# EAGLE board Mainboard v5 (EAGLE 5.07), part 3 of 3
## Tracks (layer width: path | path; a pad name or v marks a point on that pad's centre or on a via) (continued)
N$145 (continued)
  Top 0.406: IC7.10 R83.2 33.5,109.53 34.45,108.58 35.4,107.64 R77.2
N$146  (via drill 0.3)
  Top 0.254: R11.2 v86.84,75.56
  Top 0.305: R11.2
  Top 0.406: R11.2 IC1.10
  Bottom 0.254: v86.84,75.56 v86.83,75.56 R5.1
N$147  (via drill 0.3)
  Top 0.61: IC7.16 25.88,113.67 25.88,110.49 v25.88,103.19
  Bottom 0.61: v25.88,103.19 23.65,103.19 R75.1
N$148  (via drill 0.3)
  Top 0.254: v5.24,81.92 5.56,81.92 R30.2
  Bottom 0.254: M2.3 6.02,83.01 5.24,82.23 v5.24,81.92
N$149
  Top 0.254: IC37.31 94.23,14.51 94.78,13.97 96.36,13.97 97,14.61 99.22,14.61 LED11.C
N$150
  Top 0.254: C113.1 52.87,26.67 R153.1 50.33,26.35 50.01,26.35 48.78,25.13 IC31.5
N$151
  Top 0.254: R157.2 46.83,29.84 47.28,29.39 IC31.9
N$152
  Top 0.254: IC37.32 97.47,15.39 98.27,16.19 100.39,16.19 LED12.C
N$153
  Top 0.254: IC37.1 99.91,16.89 100.49,17.46 101.81,17.46 LED13.C
N$154
  Top 0.406: 35.4,111.12 R83.1 | 35.4,111.12 R87.2 | IC7.11 35.4,111.12
N$156
  Top 0.254: IC37.2 99.76,17.68 100.81,18.73 103.24,18.73 LED14.C
N$157  (via drill 0.3)
  Top 0.254: 77.31,120.97 R137.2 R136.2 | 77.31,120.97 R138.2 R134.2 R135.2 69.06,120.97 Q34.3 | 77.31,120.97 77.31,123.83 77,124.14 77,125.09 | 77,125.09 SDCARD.4 | 77,125.09 77,126.05 v77.63,126.68
  Bottom 0.254: v77.63,126.68 79.85,126.68 R133.2
N$158
  Top 0.406: FLT5.C 29.05,93.67 R73.1
N$159
  Top 0.254: IC37.9 100.69,23.98 LED15.C
N$160
  Top 0.254: IC37.10 94.23,24.86 94.46,25.08 102.28,25.08 LED16.C
N$161
  Top 0.254: IC37.11 93.44,24.7 94.46,25.72 104.33,25.72 LED17.C
N$162  (via drill 0.3)
  Top 0.61: IC7.27 23.97,99.69 v23.97,99.38
  Bottom 0.61: v23.97,99.38 23.97,98.42 R74.1
N$163
  Top 0.406: IC7.9 32.23,108.58 R77.1
N$164
  Top 0.254: IC37.12 92.64,24.85 94.14,26.35 106.39,26.35 LED18.C
N$165
  Top 0.254: IC29.24 59,105.2 59.53,105.73 59.53,107 59.53,109.22 58.26,110.49 R148.2
N$166
  Top 0.254: IC37.13 91.83,25 93.82,26.99 108.45,26.99 LED19.C
N$167
  Bottom 0.254: C141.1 R207.1
N$168
  Top 0.254: IC29.23 59.5,105.06 60.17,105.73 60.17,106.68 60.17,107.31 60.17,109.54 59.53,110.17 59.53,112.08 60.48,113.03 62.07,113.03 63.34,114.3 63.34,115.57 | 63.34,115.57 63.34,116.14 Q35.1 | C93.1 67.47,115.57 63.34,115.57
N$169
  Top 0.254: R148.1 53.75,114.68 53.75,115.57 | 53.75,115.57 Q35.2 | C94.1 49.69,115.57 53.75,115.57
N$170
  Bottom 0.254: C142.1 R208.1
N$171
  Top 0.254: R149.1 65.25,110.17 Q36.2 C96.1
N$172
  Bottom 0.254: C143.1 R209.1
N$173
  Bottom 0.406: R145.2 JTAG.11
N$174
  Top 0.254: R158.2 43.02,30.48 44.61,28.89 46.76,28.89 IC31.10
N$175  (via drill 0.3)
  Top 0.254: v44.93,29.53 C115.1
  Bottom 0.254: C115.1 44.93,30.16 v44.93,29.53
N$176
  Bottom 0.254: IC28.5 75.72,128.27 73.82,128.27 C88.1 71.92,128.91 71.92,130.18 72.87,131.13 72.87,132.4 USB.1 74.14,132.4
N$177
  Bottom 0.254: USB.2 74.77,130.18 IC28.1
N$178
  Bottom 0.254: USB.3 75.72,130.81 76.68,130.81 76.68,130.49 IC28.3
N$179
  Bottom 0.254: IC27.6 90.65,128.59 92.23,130.18 92.23,131.76 C86.1
N$180
  Bottom 0.254: IC27.2 90.65,126.05 90.97,125.73 90.97,123.51 C87.1
N$181
  Bottom 0.254: 96.05,126.68 96.02,126.66 IC27.14 97.31,126.68 98.58,127.95 98.58,129.86 94.46,133.99 93.19,133.99 92.87,134.3 92.87,138.43 92.23,139.06 88.42,139.06 PC.1
N$182
  Bottom 0.254: IC27.3 88.42,126.68 C85.2
N$183
  Bottom 0.254: IC27.1 89.38,125.41 88.42,124.46 88.11,124.46 C85.1
N$184
  Bottom 0.254: IC27.4 88.74,127.32 C89.1
N$185
  Bottom 0.254: IC27.5 89.38,127.95 89.06,128.27 89.06,128.91 C89.2
N$186
  Bottom 0.254: IC27.13 97,127.32 97.95,128.27 97.95,129.54 94.14,133.35 92.87,133.35 PC.2
N$187
  Top 0.254: R161.1 45.88,27.94 48.28,27.94 IC31.7
N$188
  Bottom 0.61: Q9.4 R28.2
N$189  (via drill 0.3)
  Top 0.61: Q10.4 v19.53,79.38
  Bottom 0.61: v19.53,79.38 R32.2
N$190
  Bottom 0.61: R34.2 19.53,81.92 Q11.4
N$191  (via drill 0.3)
  Top 0.61: Q12.4 v19.53,85.72
  Bottom 0.61: v19.53,85.72 R35.2
N$193
  Top 0.254: R125.2 53.5,37.47 Q32.B
N$194
  Top 0.254: R126.2 53.5,33.8 Q33.B
N$195
  Top 0.254: IC26.13 63.66,37.47 R125.1
N$196
  Top 0.254: IC26.14 63.66,29.21 54.77,29.21 R126.1
N$197
  Top 0.254: C111.1 46.52,22.86 47.28,23.63 IC31.2
N$198
  Top 0.254: 47.78,19.05 IC31.3 | 47.78,19.05 46.83,19.05 C111.2 44.93,19.37 43.02,17.46 42.07,17.46 L2.P$2 | D23.C 49.05,18.41 48.42,19.05 47.78,19.05
  pour Top (no thermals): 40.16,18.1 43.02,18.1 44.93,20 50.64,20 50.64,17.14 45.24,17.14 44.61,16.51 40.16,16.51
N$200  (via drill 0.3)
  Top 0.254: R159.2 v48.42,30.8 47.78,30.16 IC31.8
  Bottom 0.254: v48.42,30.8 R159.2
N$201
  Top 0.254: R167.2 arc-90 47.15,14.61 47.28,14.47 IC34.9
N$202
  Top 0.254: R168.2 43.02,14.61 44.61,13.02 46.76,13.02 IC34.10
N$203  (via drill 0.3)
  Top 0.254: v44.93,13.65 C120.1
  Bottom 0.254: C120.1 44.93,14.29 v44.93,13.65
N$204
  Top 0.254: R175.1 45.88,12.06 48.28,12.06 IC34.7
N$205
  Top 0.254: C116.1 46.52,6.99 47.28,7.75 IC34.2
N$206
  Top 0.254: 47.78,3.17 IC34.3 | 47.78,3.17 46.83,3.17 C116.2 44.93,3.49 43.34,1.91 42.39,1.91 L3.P$2 | D25.C 49.37,2.86 49.05,3.17 47.78,3.17
  pour Top (no thermals): 40.16,2.22 43.02,2.22 44.93,4.13 50.64,4.13 50.64,1.27 45.24,1.27 44.61,0.64 40.16,0.64
N$207  (via drill 0.3)
  Top 0.254: IC34.8 47.78,14.29 v48.42,14.92 R173.2
  Bottom 0.254: v48.42,14.92 R173.2
N$213
  Bottom 0.61: Q13.4 R38.2
N$215  (via drill 0.3)
  Top 0.61: Q14.4 v19.53,41.91
  Bottom 0.61: v19.53,41.91 R39.2
N$216  (via drill 0.3)
  Top 0.254: v3.97,31.43 R45.2
  Bottom 0.254: M3.2 6.32,31.88 5.88,31.43 v3.97,31.43
N$217  (via drill 0.3)
  Top 0.254: v12.86,31.43 R49.2
  Bottom 0.254: M3.4 8.32,32.48 8.73,32.07 12.23,32.07 v12.86,31.43
N$222  (via drill 0.3)
  Top 0.254: v8.41,31.43 R48.2
  Bottom 0.254: M3.3 7.32,31.89 7.78,31.43 v8.41,31.43
N$223
  Bottom 0.61: Q15.4 R46.2
N$224  (via drill 0.3)
  Top 0.61: Q16.4 v19.53,48.26
  Bottom 0.61: v19.53,48.26 R50.2
N$225
  Bottom 0.61: Q17.4 R52.2
N$226  (via drill 0.3)
  Top 0.61: Q18.4 v19.53,54.61
  Bottom 0.61: v19.53,54.61 R53.2
N$234
  Bottom 0.61: Q19.4 100.49,55.88 R56.2
N$236  (via drill 0.3)
  Top 0.61: v100.49,52.07 Q20.4
  Bottom 0.61: R57.2 v100.49,52.07
N$237  (via drill 0.3)
  Top 0.254: v103.03,33.34 R63.2
  Bottom 0.254: M4.2 105.38,32.51 104.94,32.07 103.67,32.07 103.03,32.7 v103.03,33.34
N$238  (via drill 0.3)
  Top 0.254: v111.92,31.75 111.92,33.02 112.24,33.34 R67.2
  Bottom 0.254: M4.4 107.38,32.8 108.43,31.75 v111.92,31.75
N$243  (via drill 0.3)
  Top 0.254: v107.47,31.75 107.47,33.02 107.79,33.34 R66.2
  Bottom 0.254: M4.3 106.38,32.53 107.16,31.75 v107.47,31.75
N$244
  Bottom 0.61: R64.2 Q21.4
N$245  (via drill 0.3)
  Top 0.61: v100.49,45.72 Q22.4
  Bottom 0.61: R68.2 v100.49,45.72
N$246
  Bottom 0.61: R70.2 Q23.4
N$247  (via drill 0.3)
  Top 0.61: v100.49,39.37 Q24.4
  Bottom 0.61: R71.2 v100.49,39.37
N$255
  Bottom 0.61: Q25.4 R74.2
N$257  (via drill 0.3)
  Top 0.61: Q26.4 v19.53,102.23
  Bottom 0.61: v19.53,102.23 R75.2
N$258
  Top 0.254: R81.2 10.95,117.16 8.1,117.16 M5.2
N$259
  Top 0.254: R85.2 17.3,115.89 9.05,115.89 5.88,112.71 5.88,109.86 M5.4
N$264
  Top 0.254: R84.2 14.13,116.52 8.73,116.52 5.24,113.03 5.24,111.76 M5.3
N$265
  Bottom 0.61: Q27.4 R82.2
N$266  (via drill 0.3)
  Top 0.61: Q28.4 v19.53,108.58
  Bottom 0.61: v19.53,108.58 R86.2
N$267
  Bottom 0.61: Q29.4 R88.2
N$268  (via drill 0.3)
  Top 0.61: Q30.4 v19.53,114.94
  Bottom 0.61: v19.53,114.94 R89.2
OSC32-IN
  Top 0.254: IC29.8 67,105.88 66.52,106.36 66.52,110.81 Q36.1 68.42,111.12 C95.1
OSC32-OUT
  Top 0.254: IC29.9 66.5,105.42 R149.2
PADC-VOP
  Top 0.254: 80.17,14.61 C133.1 78.58,14.61 | 75.09,14.61 78.58,14.61 | 78.58,14.61 80.17,14.61 | IC35.4 69.06,14.61 75.09,14.61 | 75.09,14.61 IC36.4 | 80.17,14.61 80.49,14.61 R192.2
PC-RXD  (via drill 0.3)
  Top 0.254: IC29.102 67.5,84.17 67.79,84.45 v67.79,88.9 | v90.97,113.67 90.97,124.46 94.78,128.27 v97,128.27
  Bottom 0.254: IC27.12 96.68,127.95 v97,128.27 | v67.79,88.9 73.5,94.61 73.5,102.23 80.49,109.22 87.79,109.22 90.97,112.39 v90.97,113.67
PC-TXD  (via drill 0.3)
  Top 0.254: IC29.101 67,84.31 67.15,84.45 v67.15,89.53 | v97,129.22 94.46,129.22 89.69,124.46 v89.69,113.67
  Bottom 0.254: IC27.11 96.05,128.59 96.36,128.59 v97,129.22 | v67.15,89.53 72.87,95.25 72.87,102.55 80.17,109.86 85.89,109.86 v89.69,113.67
PWR+
  Bottom 0.406: 42.7,3.17 38.26,7.62 F1.P$1 | BAT1+.P$1 61.75,5.71 R169.2
  pour Bottom (no thermals): 31.27,8.26 31.91,8.89 38.9,8.89 43.98,3.81 57.94,3.81 59.22,2.54 59.22,1.27 58.58,0.64 42.07,0.64 36.35,6.35 31.91,6.35 31.27,6.99
PWR-AREF
  Top 0.254: R206.1 83.03,25.72 81.12,25.72 80.57,25.17 C139.+ 80.17,24.68 80.17,22.07 D26.1 C140.1 85.57,21.91 87.39,20.09 IC37.20
PWR-AVCC
  Top 0.254: IC37.18 87.06,21.68 86.84,21.91 86.84,23.66 L4.2 87,24.13 C138.1 R206.2
PWR-CS  (via drill 0.3)
  Top 0.254: IC29.73 53.01,83.64 53.82,84.45 v56.36,84.45 | v75.09,48.26 73.19,48.26 v70.01,51.44 | v90.65,26.67 90.65,25.72 91.03,25.33 IC37.14
  Bottom 0.254: v56.36,84.45 56.99,84.45 61.12,80.33 61.12,77.47 70.01,68.26 v70.01,51.44 | v75.09,48.26 90.65,32.7 v90.65,26.67
PWR-RST  (via drill 0.3)
  Top 0.254: IC29.65 52.4,88.09 52.87,87.63 v54.77,87.63 | v75.09,49.21 73.5,49.21 v70.64,52.07 | IC37.29 92.64,14.05 v92.55,13.97 R195.1 C136.1
  Bottom 0.254: v54.77,87.63 61.75,80.64 61.75,77.47 70.64,68.58 v70.64,52.07 | v75.09,49.21 91.28,33.02 91.28,15.24 v92.55,13.97
PWR-XTAL  (via drill 0.3)
  Top 0.254: v97.95,21.91 97.73,21.68 IC37.7
  Bottom 0.254: QG2.3 98.28,22.23 v97.95,21.91
SD-CD  (via drill 0.3)
  Top 0.152: IC29.114 74.04,87.09 76.68,84.45 v77,84.45
  Top 0.254: SDCARD.CD 83.34,133.03 v84.61,133.03 84.61,128.91 88.42,125.09 v88.42,106.05
  Bottom 0.254: R133.1 84.3,133.03 v84.61,133.03 | v77,84.45 77.95,84.45 81.76,88.27 81.76,97.79 88.42,104.46 v88.42,106.05
SD-CLK  (via drill 0.3)
  Top 0.152: IC29.113 73.9,86.59 76.36,84.14 v76.36,83.82
  Top 0.254: SDCARD.5 77.95,125.73 79.22,127 82.71,127 85.89,123.83 v85.89,104.14
  Bottom 0.254: v76.36,83.82 76.36,87 77.63,87 79.85,89.22 79.85,98.74 85.25,104.14 v85.89,104.14
SD-CMD  (via drill 0.3)
  Top 0.152: IC29.116 74.94,88.09 75.09,87.95 75.09,87.31 76.04,86.36 v77,86.36
  Top 0.254: 76.04,124.97 SDCARD.3 | 76.04,124.97 R138.1 | 76.04,124.97 76.04,126.48 77.31,127.64 83.03,127.64 86.52,124.14 v86.52,103.5
  Bottom 0.254: v77,86.36 77.95,86.36 80.49,88.9 80.49,98.42 85.57,103.5 v86.52,103.5
SD-D0  (via drill 0.3)
  Top 0.254: R137.1 | R137.1 80.17,123.19 80.17,125.09 SDCARD.7 | R137.1 80.17,122.56 80.17,121.92 83.34,121.92 84.61,120.65 v84.61,111.12 | IC29.98 65.5,89.79 65.25,90.05 v65.25,91.12
  Bottom 0.254: v65.25,91.12 71.6,97.16 71.6,103.19 79.53,111.12 v84.61,111.12
SD-D1  (via drill 0.3)
  Top 0.254: SDCARD.8 81.44,125.09 81.44,123.19 81.76,122.87 R136.1 83.34,122.87 85.25,120.97 v85.25,110.49 | IC29.99 66,90.29 65.88,90.42 v65.88,90.49
  Bottom 0.254: v65.88,90.49 72.23,96.52 72.23,102.87 79.85,110.49 v85.25,110.49
SD-D2  (via drill 0.3)
  Top 0.152: IC29.111 73.63,85.59 74.45,84.77 v74.45,83.82
  Top 0.254: R135.1 73.5,124.78 SDCARD.1 73.5,125.73 76.68,128.91 83.66,128.91 87.79,124.78 v87.79,105.41
  Bottom 0.254: v74.45,83.82 74.45,87.63 77.31,90.49 77.31,92.08 78.58,93.34 78.58,99.38 84.61,105.41 v87.79,105.41
SD-D3  (via drill 0.3)
  Top 0.152: IC29.112 73.77,86.09 75.41,84.45 v75.41,83.82
  Top 0.254: R134.1 74.77,123.83 74.77,125.09 | 74.77,125.09 SDCARD.2 | 74.77,125.09 74.77,126.05 77,128.27 83.34,128.27 87.16,124.46 v87.16,104.78
  Bottom 0.254: v75.41,83.82 75.41,87.31 77.95,89.85 77.95,91.76 79.22,93.03 79.22,99.06 84.93,104.78 v87.16,104.78
SD-PWR  (via drill 0.3)
  Top 0.152: v77,85.41 76.36,85.41 74.17,87.59 IC29.115
  Top 0.254: R127.1 67.79,126.68 | 69.38,125.09 69.38,122.87 Q34.1 69.38,125.09 | 67.79,126.68 69.38,125.09 | 67.79,126.68 66.83,126.68 66.2,126.05 66.2,120.97 67.47,119.7 73.19,119.7 74.14,118.75 76.36,118.75 82.71,112.39 82.71,104.78 v85.25,102.23
  Bottom 0.254: v77,85.41 77.95,85.41 81.12,88.58 81.12,98.11 v85.25,102.23
SPI1-MISO  (via drill 0.3)
  Top 0.254: v83.66,94.61 84.93,95.89 v102.39,95.89 | v56.04,90.81 56.04,96.2 52.65,99.59 IC29.42 49.59,99.59 49.37,99.38 45.24,99.38 45.24,118.11 v46.2,119.06 | IC25.9 58.4,130.31 v58.26,130.18
  Bottom 0.254: v56.04,90.81 62.71,90.81 71.92,81.6 77.95,81.6 83.66,87.63 v83.66,94.61 | v46.2,119.06 46.2,120.02 R120.2 46.2,120.02 v46.2,119.06 | v46.2,119.06 46.83,118.43 49.69,118.43 50.33,119.06 54.45,119.06 58.58,123.19 58.58,129.22 58.26,129.54 v58.26,130.18 | v102.39,95.89 103.03,95.89 108.11,100.97 108.11,105.72 R116.1
SPI1-MOSI  (via drill 0.3)
  Top 0.254: v84.3,93.98 85.57,95.25 v103.03,95.25 | v56.67,90.17 55.41,90.17 55.41,95.89 52.2,99.09 IC29.43 49.73,99.09 49.37,98.74 44.61,98.74 44.61,118.43 v43.98,119.06 | IC25.10 59.2,130.19 v59.22,130.18
  Bottom 0.254: v56.67,90.17 62.39,90.17 71.6,80.96 78.27,80.96 84.3,87.31 v84.3,93.98 | v43.98,119.06 R121.2 v43.98,119.06 | v43.98,119.06 45.24,117.79 50.01,117.79 50.64,118.43 54.77,118.43 59.22,122.87 v59.22,130.18 | v103.03,95.25 103.35,95.25 108.75,100.65 108.75,103.82 R117.2
SPI1-SCK  (via drill 0.3)
  Top 0.254: v83.03,93.98 83.03,94.93 84.61,96.52 v101.76,96.52 | v56.67,91.44 56.67,96.52 53.1,100.09 IC29.41 49.45,100.09 49.37,100.01 45.88,100.01 45.88,117.79 v47.15,119.06 | IC25.12 60.8,130.5 v60.8,130.18
  Bottom 0.254: v56.67,91.44 63.03,91.44 72.23,82.23 77.63,82.23 83.03,87.63 v83.03,93.98 | v47.15,119.06 48.74,119.06 49.05,119.38 R119.2 49.38,120.02 54.45,120.02 57.94,123.51 57.94,128.91 57.63,129.22 57.63,130.49 57.94,130.81 60.17,130.81 v60.8,130.18 | v101.76,96.52 102.71,96.52 107.47,101.28 107.47,107.63 R115.1
SPI2-MISO  (via drill 0.3)
  Top 0.254: IC29.75 54,81.47 53.18,80.64 52.87,80.64 51.91,79.69 v51.91,75.56 | IC24.9 58.4,65.54 58.26,65.41 v58.26,64.77 | IC13.16 66.78,54.87 v66.83,54.93 | v75.09,46.35 72.55,46.35 70.01,48.9 v66.83,48.9 | v89.38,26.67 89.38,25.4 89.44,25.34 IC37.16
  Bottom 0.254: v51.91,75.56 51.91,68.26 55.41,64.77 v58.26,64.77 62.39,64.77 66.83,60.33 v66.83,54.93 v66.83,48.9 | v75.09,46.35 89.38,32.07 v89.38,26.67 89.38,9.53 90.01,8.89 R208.2
SPI2-MOSI  (via drill 0.3)
  Top 0.254: IC29.76 54.5,81.33 53.18,80.01 52.87,80.01 52.55,79.69 v52.55,74.93 | IC24.10 59.2,65.42 v59.22,65.41 | IC13.15 67.38,54.07 v67.47,53.98 | v75.09,47.31 72.87,47.31 70.64,49.53 v67.47,49.53 | v90.01,26.04 90.01,25.4 90.23,25.18 IC37.15
  Bottom 0.254: v52.55,74.93 52.55,68.58 55.72,65.41 v59.22,65.41 62.71,65.41 67.47,60.64 v67.47,53.98 v67.47,49.53 | v75.09,47.31 90.01,32.38 v90.01,26.04 90.01,10.16 91.92,8.26 R207.2
SPI2-SCK  (via drill 0.3)
  Top 0.254: IC29.74 53.5,81.6 53.18,81.28 52.87,81.28 51.28,79.69 v51.28,74.93 | IC24.12 v60.8,64.14 | IC13.17 62.8,56.52 v66.2,56.52 | v75.09,45.4 72.23,45.4 69.38,48.26 v66.2,48.26 | v88.74,26.04 88.42,25.72 88.42,22.65 IC37.17
  Bottom 0.254: v51.28,74.93 51.28,67.94 55.09,64.14 v60.8,64.14 62.07,64.14 66.2,60.01 v66.2,56.52 v66.2,48.26 | v75.09,45.4 88.74,31.75 v88.74,26.04 88.74,9.53 88.11,8.89 R209.2
SRST  (via drill 0.3)
  Top 0.254: C91.1 58.26,106.68 58.26,105.41 58.5,105.17 IC29.25 58.5,102.63 v58.9,102.23 | 91.6,107.31 RESET.4 | v91.6,113.03 91.6,107.31 | 91.6,107.31 94.14,104.78 R143.1 R147.1 | RESET.3 80.91,107.84 80.81,107.63 80.81,108.9 v78.58,111.12
  Bottom 0.254: v58.9,102.23 62.39,102.23 64.3,100.33 70.96,100.33 70.96,103.5 v78.58,111.12 78.58,111.76 81.12,114.3 91.6,114.3 v91.6,113.03
SW-HIGH  (via drill 0.81)
  Top 0.254: IC33.3 61.75,9.84 61.12,9.84 60.17,10.79 59.53,10.79 R160.2 | IC32.3 61.75,18.1 61.12,18.1 60.17,19.05 59.53,19.05 R155.1
  Bottom 0.406: D24.C 32.55,19.05 33.81,17.78 56.04,17.78
  other vias: 59.22,17.46 59.22,9.21
  pour Bottom (no thermals): 29.37,20.32 29.37,16.51 53.5,16.51 57.31,12.7 57.31,9.53 58.58,8.26 59.85,8.26 59.85,17.78 57.94,19.68 35.09,19.68 34.45,20.32
  pour Top (no thermals): 57.94,20 57.94,17.78 58.9,16.83 59.53,16.83 60.48,17.78 60.48,20
  pour Top (no thermals): 57.94,11.75 57.94,9.53 58.9,8.57 59.53,8.57 60.48,9.53 60.48,11.75
TCK  (via drill 0.3)
  Top 0.152: IC29.109 73.05,84.59
  Top 0.254: 73.05,84.59 72.55,84.59 v72.55,83.82 | v92.87,112.39 R141.1
  Bottom 0.254: v72.55,83.82 72.55,88.27 76.04,91.76 76.04,98.74 83.98,106.68 87.16,106.68 v92.87,112.39
TDI  (via drill 0.3)
  Top 0.254: IC29.110 73.5,85.09 v73.5,83.82 | v93.5,114.3 93.5,116.2 94.78,117.47 R139.1
  Bottom 0.254: v73.5,83.82 73.5,87.95 76.68,91.12 76.68,92.08 77.95,93.34 77.95,99.69 84.3,106.05 87.47,106.05 93.5,112.08 v93.5,114.3
TDO  (via drill 0.3)
  Top 0.152: 74.38,96.59 74.53,96.59
  Top 0.254: IC29.133 74.38,96.59 | 74.53,96.59 75.09,97.16 v87.16,97.16 | v96.05,106.05 96.05,107 R142.1
  Bottom 0.254: v87.16,97.16 v96.05,106.05
TMS  (via drill 0.3)
  Top 0.254: IC29.105 69,83.77 69.69,84.45 v69.69,87 | v92.23,113.67 94.14,113.67 95.41,114.94 R140.1
  Bottom 0.254: v69.69,87 75.09,92.08 75.41,92.39 75.41,100.33 82.39,107.31 86.84,107.31 92.23,112.71 v92.23,113.67
TRST  (via drill 0.3)
  Top 0.254: IC29.134 74.08,97.09 74.77,97.79 v86.52,97.79 | v95.41,118.75 95.41,120.02 R132.1
  Bottom 0.254: v86.52,97.79 95.41,106.68 v95.41,118.75
USB-DM  (via drill 0.3)
  Top 0.254: IC29.103 68,84.04 68.42,84.45 v68.42,88.27 | v75.72,119.7 76.36,119.7 83.34,112.71 v83.34,108.58
  Bottom 0.254: 74.77,126.68 IC28.6 | 74.77,126.68 75.41,126.36 75.72,126.36 v75.72,119.7 | 74.77,126.68 74.77,127 | v68.42,88.27 74.14,93.98 74.14,101.92 80.81,108.58 v83.34,108.58
USB-DP  (via drill 0.3)
  Top 0.254: IC29.104 68.5,83.9 69.06,84.45 v69.06,87.63 | v77.63,120.02 77.63,119.38 83.98,113.03 v83.98,107.95
  Bottom 0.254: IC28.4 R146.1 76.68,124.78 76.68,120.97 v77.63,120.02 | v69.06,87.63 74.77,93.34 74.77,101.6 81.12,107.95 v83.98,107.95
USB-EN  (via drill 0.3)
  Top 0.254: IC29.132 71.07,96.09 69.06,98.11 69.06,101.92 v69.69,102.55
  Bottom 0.254: R146.2 74.77,119.38 74.77,108.27 69.69,103.19 v69.69,102.55
VCC  (via drill 0.3, 0.81)
  Top 0.254: IC30.4 61.75,23.18 61.75,22.86 60.8,21.91 59.27,21.91 R152.2
  Top 0.305: C2.1 v84.93,70.48
  Top 0.406: IC7.1 29.69,98.42 v29.69,97.47 | IC2.1 v32.23,69.22 C13.1 | FLT2.A 31.91,88.27 v30.64,87 | FLT4.A v98.27,29.84 | C36.1 IC6.1 90.97,55.88 91.6,55.24 v91.6,53.98 | FLT1.A 85.89,85.72 IC1.1 | C25.1 32.87,38.42 33.81,39.37 36.04,39.37 36.04,35.56 FLT3.A
  Top 0.61: v91.6,83.82 91.6,85.72 IC1.1 | FLT5.A 29.05,95.89 27.78,95.89 v27.78,93.34 26.2,93.34 C47.1 | C25.1 IC5.1 28.42,38.1 v28.42,40.01
  Top 1.219: C50.1 C46.B | C16.1 C12.A | C28.1 C24.A | C35.B C39.1 | C1.A C5.1
  Supply 0.61: KDPWR.2 30.64,3.81 29.37,3.81 KDPWR.1
  Bottom 0.305: v84.93,70.48 89.69,70.48 89.69,70.8
  Bottom 0.406: v30.64,87 30.64,85.09 29.69,84.14 | 90.33,53.98 v91.6,53.98
  Bottom 0.61: 91.81,81.92 D1.A 91.39,81.92 89.69,81.92 | 91.71,76.52 D2.A 91.39,76.2 89.69,76.2 | 91.71,70.8 D3.A 91.39,70.69 91.28,70.8 89.69,70.8 | 89.69,70.8 89.69,76.2 | 89.69,76.2 89.69,81.92 | 89.69,70.8 89.69,68.26 101.44,68.26 | 89.69,81.92 89.69,83.82 v91.6,83.82 | 28.3,73.03 D5.A 28.42,73.03 29.69,73.03 | 28.3,78.42 D6.A 28.42,78.42 29.69,78.42 | 28.3,84.14 D7.A 28.42,84.14 29.69,84.14 29.69,78.42 | 91.81,40.64 D15.A 91.6,41.27 90.33,41.27 90.33,46.67 | 91.71,46.67 D14.A 91.6,46.67 90.33,46.67 | 91.71,52.39 D13.A 91.6,52.39 90.33,52.39 | 28.3,101.92 D17.A 28.42,101.6 29.69,101.6 | 28.3,113.35 D19.A 28.42,113.03 29.69,113.03 29.69,107.63 | 28.1,107.63 28.24,107.5 D18.A 28.42,107.63 29.69,107.63 | 29.69,101.6 v29.69,97.47 29.69,93.34 v27.78,93.34 C46.B | 29.69,101.6 29.69,107.63 | 29.69,68.58 29.69,73.03 | 29.69,73.03 29.69,78.42 | 29.69,68.58 26.83,68.58 26.2,67.94 19.21,67.94 18.57,67.31 | 29.69,68.58 32.23,68.58 v32.23,69.22 | 29.69,47.31 29.69,41.59 28.3,41.59 D9.A v28.42,40.01 | 29.69,47.31 29.69,53.02 | 29.69,53.02 29.69,55.56 29.37,55.88 19.21,55.88 | 29.69,47.31 28.42,47.31 D10.A | 29.69,53.02 28.42,53.02 D11.A | 90.33,46.67 90.33,52.39 | 90.33,52.39 90.33,53.98 90.33,56.83 95.41,56.83 95.73,57.15 101.12,57.15
  other vias: 59.85,23.81 58.58,23.81 58.58,25.08 59.85,25.08
  pour Bottom (no thermals): 12.86,115.25 10.95,115.25 10.95,95.25 16.67,95.25 16.67,92.71 19.21,92.71 19.21,97.47 12.86,97.47
  pour Bottom (no thermals): 12.86,86.04 10.95,86.04 10.95,65.41 17.3,65.41 17.3,63.5 19.21,63.5 19.21,67.94 12.86,67.94
  pour Bottom (no thermals): 10.95,37.78 12.86,37.78 12.86,55.56 19.21,55.56 19.21,60.33 16.99,60.33 16.99,58.42 10.95,58.42
  pour Bottom (no thermals): 109.06,39.05 107.16,39.05 107.16,56.83 100.81,56.83 100.81,61.59 102.39,61.59 102.39,59.69 109.06,59.69
  pour Bottom (no thermals): 109.06,86.04 107.16,86.04 107.16,68.26 100.81,68.26 100.81,63.5 102.39,63.5 102.39,65.41 109.06,65.41
  pour Supply (no thermals): 9.68,118.11 19.84,118.11 19.84,34.92 33.81,20.95 59.22,20.95 54.14,15.88 38.26,15.88 38.26,1.27 26.83,1.27 26.83,16.51 9.68,33.66
  pour Supply (no thermals): 100.49,70.48 100.49,37.47 96.68,33.66 65.56,33.66 52.87,20.95 59.22,20.95 67.47,29.21 103.03,29.21 110.65,36.83 110.65,70.48
  pour Top (no thermals): 57.94,21.27 57.94,25.4 58.26,25.72 60.17,25.72 60.48,25.4 60.48,21.27
VCC-A  (via drill 0.3)
  Top 0.254: C128.1 85.89,18.1 v86.52,18.1 86.91,18.48 IC37.22
  Bottom 0.254: v86.52,18.1 85.89,18.1 C128.1
VCC-HIGH  (via drill 0.81)
  Top 0.254: IC30.3 61.75,26.35 61.12,26.35 59.85,27.62 59.27,27.62 R152.1
  Bottom 0.406: SW3.1 31.27,26.67 D24.A 34.45,26.67 37.62,23.5 55.41,23.5
  other vias: 56.36,26.67 56.36,25.4 55.09,26.67 55.09,25.4
  pour Bottom (no thermals): 23.02,27.3 24.29,28.57 35.72,28.57 39.53,24.77 52.55,24.77 55.09,27.3 56.99,27.3 56.99,24.77 53.82,21.59 29.37,21.59 26.2,24.77 24.29,24.77 23.02,26.04
  pour Top (no thermals): 60.8,28.57 56.36,28.57 54.45,26.67 54.45,25.4 55.09,24.77 56.99,24.77 56.99,26.35 57.31,26.67 60.8,26.67
VCC-SHUNT  (via drill 0.3)
  Top 0.254: IC30.1 63.66,26.04 64.93,26.04 R154.2 69.69,25.72 v73.82,21.59
  Bottom 0.254: v73.82,21.59 R191.1

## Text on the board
tPlace: - | Tx | Rx | + | - | + | - | - | +
tNames: Mainboard v5 | Design: A.Ryll | Tigers Mannheim | BAT A | BAT B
